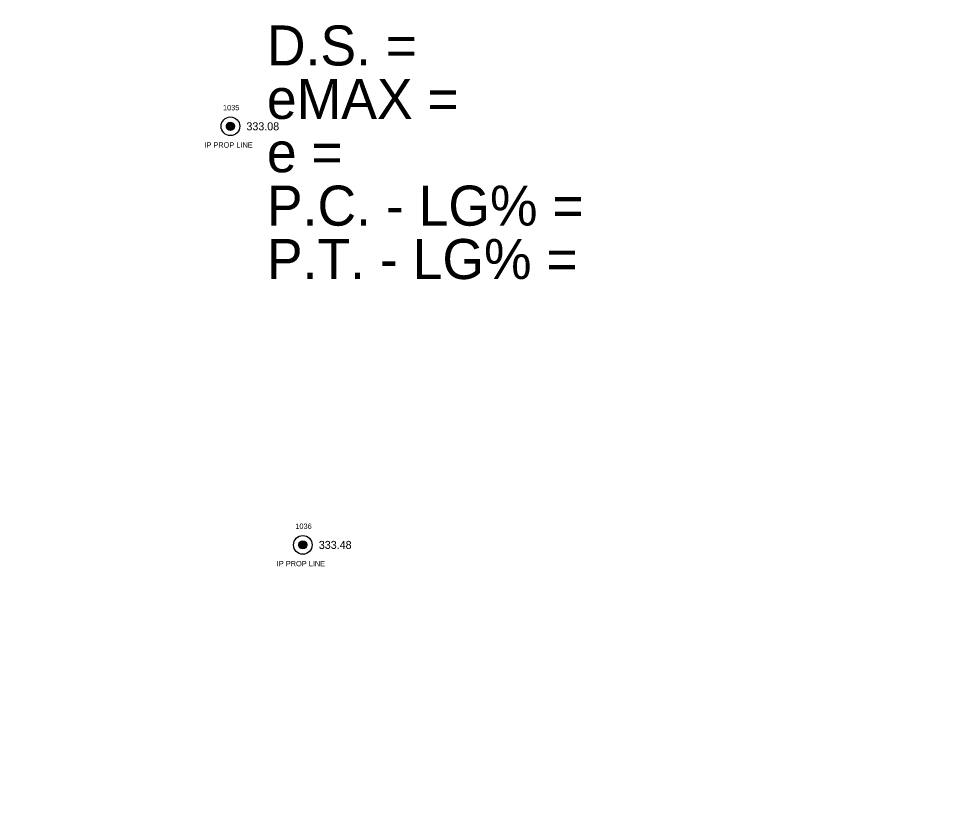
# Model space of a CAD drawing. Extents: x 1865045 to 1867370, y 910391 to 914218.
# Drawn here: x 1866779.5 to 1866955.2, y 913402.1 to 913547.8 of the extents above; entities that cross this region are included whole.
import ezdxf

# ---------------------------------------------------------------- set-up
doc = ezdxf.new("R2010")
doc.units = 0
for name, color, linetype in [('RD_EX_DV_Prop_txCode', 7, 'Continuous'), ('RD_EX_DV_PropPin', 7, 'Continuous'), ('RD_EX_TX_DV_Prop_ELEV', 7, 'Continuous'), ('RD_HC_Cl', 7, 'Continuous'), ('RD_HC_Data', 7, 'Continuous'), ('RD_SMD_Locator', 7, 'Continuous')]:
    doc.layers.add(name, color=color, linetype=linetype)

msp = doc.modelspace()

# ---------------------------------------------------------------- linework, layer by layer
at = {"layer": 'RD_EX_DV_PropPin'}
for p, q in [((1866818.42, 913527.41), (1866818.42, 913527.81)), ((1866818.46, 913527.31), (1866818.46, 913527.91)), ((1866818.49, 913527.24), (1866818.49, 913527.98)), ((1866818.53, 913527.18), (1866818.53, 913528.04)), ((1866818.56, 913527.14), (1866818.56, 913528.08)), ((1866818.6, 913527.09), (1866818.6, 913528.12)), ((1866818.63, 913527.06), (1866818.63, 913528.16)), ((1866818.67, 913527.03), (1866818.67, 913528.19)), ((1866818.7, 913527), (1866818.7, 913528.22)), ((1866818.74, 913526.98), (1866818.74, 913528.24)), ((1866818.77, 913526.95), (1866818.77, 913528.27)), ((1866818.81, 913526.93), (1866818.81, 913528.29)), ((1866818.84, 913526.92), (1866818.84, 913528.3)), ((1866818.88, 913526.9), (1866818.88, 913528.32)), ((1866818.91, 913526.89), (1866818.91, 913528.33)), ((1866818.95, 913526.88), (1866818.95, 913528.34)), ((1866818.98, 913526.87), (1866818.98, 913528.35)), ((1866819.02, 913526.86), (1866819.02, 913528.36)), ((1866819.05, 913526.86), (1866819.05, 913528.36)), ((1866819.09, 913526.85), (1866819.09, 913528.37)), ((1866819.12, 913526.85), (1866819.12, 913528.37)), ((1866819.16, 913526.85), (1866819.16, 913528.37)), ((1866819.19, 913526.85), (1866819.19, 913528.37)), ((1866819.23, 913526.85), (1866819.23, 913528.37)), ((1866819.26, 913526.86), (1866819.26, 913528.36)), ((1866819.3, 913526.86), (1866819.3, 913528.36)), ((1866819.33, 913526.87), (1866819.33, 913528.35)), ((1866819.37, 913526.88), (1866819.37, 913528.34)), ((1866819.4, 913526.89), (1866819.4, 913528.33)), ((1866819.44, 913526.9), (1866819.44, 913528.32)), ((1866819.47, 913526.92), (1866819.47, 913528.3)), ((1866819.51, 913526.93), (1866819.51, 913528.29)), ((1866819.54, 913526.95), (1866819.54, 913528.27)), ((1866819.58, 913526.98), (1866819.58, 913528.24)), ((1866819.61, 913527), (1866819.61, 913528.22)), ((1866819.65, 913527.03), (1866819.65, 913528.19)), ((1866819.68, 913527.06), (1866819.68, 913528.16)), ((1866819.72, 913527.09), (1866819.72, 913528.12)), ((1866819.75, 913527.14), (1866819.75, 913528.08)), ((1866819.79, 913527.18), (1866819.79, 913528.04)), ((1866819.82, 913527.24), (1866819.82, 913527.98)), ((1866819.86, 913527.31), (1866819.86, 913527.91)), ((1866819.89, 913527.41), (1866819.89, 913527.81)), ((1866832.07, 913448.83), (1866832.07, 913449.57)), ((1866832.1, 913448.77), (1866832.1, 913449.63)), ((1866832.14, 913448.72), (1866832.14, 913449.67)), ((1866832.17, 913448.68), (1866832.17, 913449.71)), ((1866832.21, 913448.65), (1866832.21, 913449.75)), ((1866832.24, 913448.62), (1866832.24, 913449.78)), ((1866832.28, 913448.59), (1866832.28, 913449.81)), ((1866832.31, 913448.56), (1866832.31, 913449.83)), ((1866832.35, 913448.54), (1866832.35, 913449.86)), ((1866832.38, 913448.52), (1866832.38, 913449.87)), ((1866832.42, 913448.51), (1866832.42, 913449.89)), ((1866832.45, 913448.49), (1866832.45, 913449.91)), ((1866832.49, 913448.48), (1866832.49, 913449.92)), ((1866832.52, 913448.47), (1866832.52, 913449.93)), ((1866832.56, 913448.46), (1866832.56, 913449.94)), ((1866832.59, 913448.45), (1866832.59, 913449.95)), ((1866832.63, 913448.45), (1866832.63, 913449.95)), ((1866832.66, 913448.44), (1866832.66, 913449.96)), ((1866832.7, 913448.44), (1866832.7, 913449.96)), ((1866832.73, 913448.44), (1866832.73, 913449.96)), ((1866832.77, 913448.44), (1866832.77, 913449.96)), ((1866832.8, 913448.44), (1866832.8, 913449.96)), ((1866832.84, 913448.45), (1866832.84, 913449.95)), ((1866832.87, 913448.45), (1866832.87, 913449.95)), ((1866832.91, 913448.46), (1866832.91, 913449.94)), ((1866832.94, 913448.47), (1866832.94, 913449.93)), ((1866832.98, 913448.48), (1866832.98, 913449.92)), ((1866833.01, 913448.49), (1866833.01, 913449.91)), ((1866833.05, 913448.51), (1866833.05, 913449.89)), ((1866833.08, 913448.52), (1866833.08, 913449.87)), ((1866833.12, 913448.54), (1866833.12, 913449.86)), ((1866833.15, 913448.56), (1866833.15, 913449.83)), ((1866833.19, 913448.59), (1866833.19, 913449.81)), ((1866833.22, 913448.62), (1866833.22, 913449.78)), ((1866833.26, 913448.65), (1866833.26, 913449.75)), ((1866833.29, 913448.68), (1866833.29, 913449.71)), ((1866833.33, 913448.72), (1866833.33, 913449.67)), ((1866833.36, 913448.77), (1866833.36, 913449.63)), ((1866833.4, 913448.83), (1866833.4, 913449.57)), ((1866832, 913449), (1866832, 913449.4)), ((1866832.03, 913448.9), (1866832.03, 913449.5)), ((1866833.43, 913448.9), (1866833.43, 913449.5)), ((1866833.47, 913449), (1866833.47, 913449.4))]:
    msp.add_line(p, q, dxfattribs=at)
for centre, radius in [((1866819.16, 913527.61), 1.75), ((1866819.16, 913527.61), 0.761), ((1866832.73, 913449.2), 1.75), ((1866832.73, 913449.2), 0.761)]:
    msp.add_circle(centre, radius, dxfattribs=at)
at = {"layer": 'RD_HC_Cl'}
msp.add_arc((1866091.29, 914128.71), 889.35, 305.21546, 346.25455, dxfattribs=at)
at = {"layer": 'RD_SMD_Locator'}
for centre in [(1866819.16, 913527.61), (1866832.73, 913449.2)]:
    msp.add_circle(centre, 0.15, dxfattribs=at)

# ---------------------------------------------------------------- texts
at = {"layer": 'RD_EX_DV_Prop_txCode'}
for s, p in [('1035', (1866817.77, 913530.61)), ('IP PROP LINE', (1866814.28, 913523.61)), ('1036', (1866831.32, 913452.2)), ('IP PROP LINE', (1866827.85, 913445.2))]:
    msp.add_text(s, height=1, dxfattribs=at).set_placement(p)
at = {"layer": 'RD_EX_TX_DV_Prop_ELEV'}
for s, p in [('333.08', (1866822.16, 913526.86)), ('333.48', (1866835.73, 913448.45))]:
    msp.add_text(s, height=1.5, dxfattribs=at).set_placement(p)
at = {"layer": 'RD_HC_Data'}
for s, p in [('D.S. = ', (1866826, 913539)), ('eMAX = ', (1866826, 913529)), ('e = ', (1866826, 913519)), ('P.C. - LG% = ', (1866826, 913509)), ('P.T. - LG% = ', (1866826, 913499))]:
    msp.add_text(s, height=7.5, dxfattribs=at).set_placement(p)

doc.saveas('drawing.dxf')
